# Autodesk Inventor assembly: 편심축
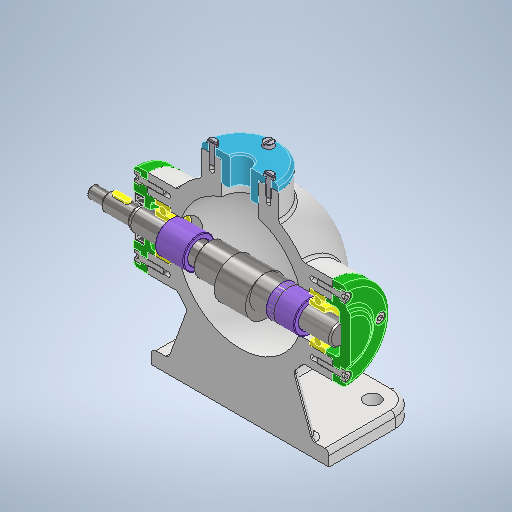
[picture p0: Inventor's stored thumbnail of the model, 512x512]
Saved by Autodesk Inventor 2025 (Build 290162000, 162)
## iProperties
Created: 2024-07
Part Number: 편심축
Material: 강철, 연강
Document SubType Name: Modeling
Designer: song
Density: 7.86 g/cm^3
Appearance: 기본값
Author: jhkim
Sending System: Autodesk Inventor 2025
Preprocessor: ST-DEVELOPER v20
Part Number: 볼트 M4 x 16
Material: 스테인리스강
Description: 6각 소켓 머리 캡 나사
Density: 8.08 g/cm^3
Part Number: 볼트 M4 x 12
Description: 6각머리 태핑 나사
Density: 7.85 g/cm^3
Part Number: 앞커버
Material: 알루미늄 6061
Density: 2.71 g/cm^3
Part Number: 칼라
Part Number: 키 4 x 4 x 12
Description: 키 및 해당 키홈
Part Number: 오일실 15 30 7
Material: 고무
Description: 오일-실
Density: 0.93 g/cm^3
Part Number: 상부커버
Part Number: 베어링 - 6202
Material: 강, 연강
Description: 깊은 그루브 볼 베어링
Part Number: 뒤커버
Part Number: 조립품
Document SubType Name: Assembly
Author: song
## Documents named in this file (22)
- **C:\Users\shmin\OneDrive\바탕 화면\740708V1008\조립품.iam*LocalDocs*xAaaaq0daAaaaaaaaAaaaqx2wAf*편심축.ipt
- **C:\Users\shmin\OneDrive\바탕 화면\740708V1008\조립품.iam*LocalDocs*xAaaaapcaAaaaaaaaAaaaac1wAh*볼트 M4 x 16.ipt
- **C:\Users\shmin\OneDrive\바탕 화면\740708V1008\조립품.iam*LocalDocs*xAaaaacaaAaaaaaaaAaaaa3h5Ga*볼트 M4 x 12.ipt
- **C:\Users\shmin\OneDrive\바탕 화면\740708V1008\조립품.iam*LocalDocs*xAaaaa3aaAaaaaaaaAaaaq03eNd*앞커버.ipt
- **C:\Users\shmin\OneDrive\바탕 화면\740708V1008\조립품.iam*LocalDocs*xAaaaawbaAaaaaaaaAaaaq23uXb*칼라.ipt
- **C:\Users\shmin\OneDrive\바탕 화면\740708V1008\조립품.iam*LocalDocs*xAaaaqndaAaaaaaaaAaaaqdlgRa*키 4 x 4 x 12.ipt
- **C:\Users\shmin\OneDrive\바탕 화면\740708V1008\조립품.iam*LocalDocs*xAaaaqmaaAaaaaaaaAaaaqevtHc*오일실 15 30 7.ipt
- **C:\Users\shmin\OneDrive\바탕 화면\740708V1008\조립품.iam*LocalDocs*xAaaaqkbaAaaaaaaaAaaaaxicRh*상부커버.ipt
- **C:\Users\shmin\OneDrive\바탕 화면\740708V1008\조립품.iam*LocalDocs*xAaaaqxdaAaaaaaaaAaaaq2nzIb*베어링- 6202.ipt
- **C:\Users\shmin\OneDrive\바탕 화면\740708V1008\조립품.iam*LocalDocs*xAaaaqrcaAaaaaaaaAaaaahqyVe*뒤커버.ipt
- C:\Users\shmin\OneDrive\바탕 화면\740708V1008\조립품.iam
- C:\Users\shmin\OneDrive\바탕 화면\740708V1008\본체.ipt
- C:\Users\shmin\OneDrive\바탕 화면\740708V1008\뒤커버.stp
- C:\Users\shmin\OneDrive\바탕 화면\740708V1008\볼트 M4 x 16.stp
- C:\Users\shmin\OneDrive\바탕 화면\740708V1008\앞커버.stp
- C:\Users\shmin\OneDrive\바탕 화면\740708V1008\상부커버.stp
- C:\Users\shmin\OneDrive\바탕 화면\740708V1008\볼트 M4 x 12.stp
- C:\Users\shmin\OneDrive\바탕 화면\740708V1008\베어링- 6202.stp
- C:\Users\shmin\OneDrive\바탕 화면\740708V1008\오일실 15 30 7.stp
- C:\Users\shmin\OneDrive\바탕 화면\740708V1008\편심축.stp
- C:\Users\shmin\OneDrive\바탕 화면\740708V1008\칼라.stp
- C:\Users\shmin\OneDrive\바탕 화면\740708V1008\키 4 x 4 x 12.stp
